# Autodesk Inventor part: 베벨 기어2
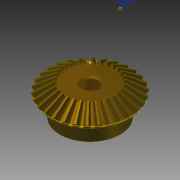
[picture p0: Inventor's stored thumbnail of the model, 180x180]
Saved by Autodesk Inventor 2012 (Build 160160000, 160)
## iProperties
Created: 2012-07
Part Number: 베벨 기어2
Material: Steel, Mild
Document SubType Name: Modeling
Designer: SeoGD™ [www.esajin.kr]
Categories: <?xml version="1.0" encoding="UTF-16"?> <MemberInstance><Categories><FamilyTemplate><FamilyTemplateParameter ValueType="xs:double" Id="1" ObjectReferenceKey="da
Mass: 60.9118 g
Surface Area: 34.3074 cm^2
Volume: 7.7496 cm^3
Density: 7.86 g/cm^3
CustomPartVersion: 1
Author: SeoGD™ [www.esajin.kr]
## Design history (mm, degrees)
node "맨 위 점"
node "메쉬 평면2"
sketch "톱니 본체 스케치"
  geometry: L1 (0, 0)-(28.669, -21.997); L2 (28.669, -21.997)-(31.109, -18.336); L3 (31.109, -18.336)-(0, 0); L4 (30, -20)-(0, 0); L5 (17.219, -13.212)-(18.685, -11.013); L6 (28.669, -21.997)-(17.219, -13.212); L7 (31.109, -18.336)-(18.685, -11.013); L8 (0, -39.387)-(0, 6.564) reference; L9 (0, -20)-(31.109, -20)
  constraints: 16 end point, 4 point on line, 3 perpendicular, 2 collinear, 1 horizontal alignment, 1 vertical alignment
  dimensions: "d0" = 60 diameter of L4.start L8 (= da_de); "d1" = 57.33744 diameter of L1.end L8 (= da_dfe); "d2" = 62.2188 diameter of L2.end L8 (= da_dae); "d3" = 14.4 distance between parallel lines of L2 L5 (= da_b); "d4" = 18.3359 vertical distance of L2.end L1.start (= da_ve)
revolve "톱니 본체" sketch "톱니 본체 스케치" stored, may be unused: angle "d5" = 90 deg
node "시작점"
node "톱니 평면"
sketch "시작 스케치"
  geometry: L1 (0, -23.505)-(0, 10.645) reference; L2 (-0.709, -2.928)-(0.709, -2.928); A1 r 19.188 centre (-19.457, -7.014) between (-0.709, -2.928) and (-3.232, 3.229); A2 r 19.188 centre (19.457, -7.014) between (3.232, 3.229) and (0.709, -2.928); A3 r 57.403 centre (0, -54.083) between (3.232, 3.229) and (-3.232, 3.229); 1 further point
  constraints: 6 point on circle, 3 centre point, 3 symmetric about line, 2 end point, 1 coincident, 1 perpendicular, 1 other
  dimensions: "d7" = 19.18795 radius of A1 (= fd_rr); "d8" = 19.45712 horizontal distance of point (0, -54.083) A1.centre (= fd_x); "d9" = 47.06905 vertical distance of point (0, -54.083) A1.centre (= fd_y); "d57" = 57.40327 radius of A3 (= 0.5 x fd_dva + 0.3 x da_he); "d58" = 51.15527 distance from line of A3.centre L2 (= 0.5 x fd_dva - 1.12 x da_he)
node "끝점"
  node "끝 평면"
sketch "3D 스케치 오른쪽"
  node "Helical Curve Right" dims "d65" = 229.90621 (computed from da_dm, da_delta, da_beta), "d66" = 31.5, "d67" = 60 (= da_de), "d68" = -9.82794 (= -da_delta), "d69" = 8.10972 (computed from fd_loft, da_delta)
node "끝 평면 오른쪽"
sketch "끝 스케치 오른쪽"
  geometry: L1 (0, -41.54)-(0, 13.178) reference; L2 (-0.422, -1.69)-(0.422, -1.69); A1 r 11.427 centre (-11.587, -4.123) between (-0.422, -1.69) and (-1.925, 1.977); A2 r 11.427 centre (11.587, -4.123) between (1.925, 1.977) and (0.422, -1.69); A3 r 34.184 centre (0, -32.153) between (1.925, 1.977) and (-1.925, 1.977); 1 further point
  constraints: 6 point on circle, 3 centre point, 3 symmetric about line, 2 end point, 1 coincident, 1 perpendicular, 1 other
  dimensions: "d70" = 11.58699 horizontal distance of A3.centre A1.centre (computed from fd_x, fd_ratio); "d71" = 28.03028 vertical distance of point (0, -32.153) A1.centre (computed from fd_y, fd_ratio); "d72" = 11.4267 radius of A1 (computed from fd_rr, fd_ratio); "d73" = 30.46369 distance from line of point (0, -32.153) L2 (computed from d58, fd_ratio); "d74" = 34.18446 radius of A3 (computed from d57, fd_ratio)
feature "로프트 오른쪽" sketch "끝 스케치 오른쪽" dims "d75" = 0, "d77" = 0, "d79" = 0, "d80" = 90 deg, "d85" = 20, "d92" = 90 deg, "d93" = 90 deg, "da_teethtype" = 0 [user parameter]
sketch "3D 스케치 왼쪽"
  node "Helical Curve Left" dims "d26" = 229.90621 (computed from da_dm, da_delta, da_beta), "d27" = 8.10972 (computed from fd_loft, da_delta), "d28" = 60 (= da_de), "d29" = -9.82794 (= -da_delta)
node "끝 평면 왼쪽"
sketch "끝 스케치 왼쪽" dims "d56" = 10.3728 (derived)
  geometry: L1 (0, -43.753)-(0, 15.405) reference; L2 (-0.422, -1.678)-(0.422, -1.678); A1 r 11.427 centre (-11.587, -4.111) between (-0.422, -1.678) and (-1.925, 1.988); A2 r 11.427 centre (11.587, -4.111) between (1.925, 1.988) and (0.422, -1.678); A3 r 34.184 centre (0, -32.142) between (1.925, 1.988) and (-1.925, 1.988); 2 further points; 1 other entity
  constraints: 6 point on circle, 3 centre point, 3 symmetric about line, 2 end point, 1 coincident, 2 other
  dimensions: "d30" = 11.4267 radius of A1 (computed from fd_rr, fd_ratio); "d31" = 11.58699 horizontal distance of point (0, -32.142) A1.centre (computed from fd_x, fd_ratio); "d32" = 28.03028 vertical distance of A1.centre point (0, -32.142) (computed from fd_y, fd_ratio); "d61" = 34.18446 radius of A3 (computed from d57, fd_ratio); "d62" = 30.46369 distance from line of point (0, -32.142) L2 (computed from d58, fd_ratio)
feature "로프트 왼쪽" sketch "끝 스케치 왼쪽" dims "d35" = 0, "d37" = 0, "d39" = 0, "d40" = 90 deg, "d84" = 10, "d90" = 90 deg, "d91" = 90 deg, "da_teethtype" = 0 [user parameter]
sketch "본체 스케치"
  geometry: L1 (0, -35.038)-(0, -19.531) reference; L2 (28.669, -21.997)-(17.219, -13.212) reference; L3 (17.219, -13.212)-(0, -13.212); L4 (28.669, -21.997)-(0, -21.997)
  constraints: 4 end point, 2 perpendicular, 2 point on line
revolve "본체 고정" sketch "본체 스케치" stored, may be unused: angle "d46" = 90 deg
sketch "Sketch6"
  geometry: L1 (30, -20)-(0, 0) reference; L2 (0, -37.8)-(0, 6.3) reference
feature "피치 지름" sketch "Sketch6" dims angle "d47" = 90 deg
sketch "스케치8"
  geometry: C1 r 22.5 at (0, 0); 1 further point
  constraints: 1 centre point, 1 coincident
  dimensions: "d94" = 45 diameter of C1
extrude "돌출1" join sketch "스케치8" distance "d95" = 13; taper "d96" = 0 deg
sketch "스케치9"
  geometry: 1 further point
hole "구멍1" sketch "스케치9" at (0, 0) diameter "d97" = 12; stored, may be unused: countersink angle "d101" = 90 deg, drill point angle "d103" = 118 deg; dims "d98" = 6, "d99" = 4, "d100" = 2, "d102" = 8
sketch "스케치10"
  geometry: L1 (5.657, 2)-(7.8, 2); L2 (7.8, 2)-(7.8, -2); L3 (7.8, -2)-(5.657, -2); A1 r 6 centre (0, 0) between (5.657, 2) and (5.657, -2) reference; 1 further point
  constraints: 6 end point, 2 parallel, 2 point on circle, 1 horizontal, 1 perpendicular
  dimensions: "d104" = 4 distance of L1.end L2.end; "d112" = 13.8 dimension on A1 L2
extrude "돌출2" cut sketch "스케치10" stored distance "d106" = 10; taper "d107" = 0 deg
chamfer "모따기1" distance "d108" = 1; stored, may be unused: second distance "d109" = 2, angle "d110" = 45 deg
fillet "모깎기1" dims "d111" = 2
body "Solid1"
feature "로프트" dims "d17" = 0, "d18" = 90 deg, "d19" = 0, "d20" = 90 deg, "d89" = 0, "da_teethtype" = 0 [user parameter]
pattern_circular "원형 패턴" dims angle "d22" = 360 deg, "d88" = 0, "da_teethtype" = 0 [user parameter]
pattern_circular "원형 패턴 오른쪽" dims angle "d82" = 360 deg, "da_teethtype" = 0 [user parameter]
pattern_circular "원형 패턴 왼쪽" dims angle "d42" = 360 deg, "da_teethtype" = 0 [user parameter]
sketch "끝 스케치"
  geometry: L1 (0, -15.359)-(0, 6.983) reference; L2 (-0.422, -1.69)-(0.422, -1.69); A1 r 11.427 centre (-11.587, -4.123) between (-0.422, -1.69) and (-1.925, 1.977); A2 r 11.427 centre (11.587, -4.123) between (1.925, 1.977) and (0.422, -1.69); A3 r 34.184 centre (0, -32.153) between (1.925, 1.977) and (-1.925, 1.977); 1 further point
  constraints: 6 point on circle, 3 centre point, 3 symmetric about line, 2 end point, 1 coincident, 1 other
  dimensions: "d12" = 11.4267 radius of A1 (computed from fd_rr, fd_ratio); "d15" = 11.58699 horizontal distance of A1.centre point (0, -32.153) (computed from fd_x, fd_ratio); "d16" = 28.03028 vertical distance of A1.centre point (0, -32.153) (computed from fd_y, fd_ratio); "d59" = 34.18446 radius of A3 (computed from d57, fd_ratio); "d60" = 30.46369 distance from line of A3.centre L2 (computed from d58, fd_ratio)
body "Srf1"
other parameters: "da_b" = 14.4 [user parameter; used in 2 equation terms], "da_de" = 60 [user parameter; used in 4 equation terms], "da_dae" = 62.2188 [user parameter; used in 2 equation terms], "da_dfe" = 57.33744 [user parameter; used in 1 equation term], "da_le" = 36.05551 [user parameter; used in 1 equation term], "da_omega" = 90 deg [user parameter; used in 1 equation term], "da_beta" = 0 [user parameter; used in 2 equation terms], "da_delta" = 9.82794 [user parameter; used in 8 equation terms], "da_alpha" = 20 deg [user parameter; used in 2 equation terms], "da_he" = 4.4 [user parameter; used in 4 equation terms], "da_ve" = 18.3359 [user parameter; used in 1 equation term], "fd_dv" = 108.16654 (computed from da_de, da_delta) [user parameter; used in 1 equation term], "fd_dva" = 112.16654 (computed from da_dae, da_delta) [user parameter; used in 3 equation terms], "fd_dvb" = 101.6433 (computed from fd_dv, da_alpha) [user parameter; used in 2 equation terms], "da_zv" = 540.83269 [user parameter; used in 1 equation term], "fd_loft" = 14.62 (= da_b + 0.05 x da_he) [user parameter; used in 4 equation terms], "fd_ratio" = 5.95514 (computed from da_le, fd_loft) [user parameter; used in 15 equation terms], "fd_rr" = 19.18795 (computed from fd_dd, fd_dvb) [user parameter; used in 6 equation terms], "fd_angle" = 0.29367 (computed from da_zv) [user parameter; used in 4 equation terms], "fd_x1" = 1.58802 (computed from da_dvw, fd_angle) [user parameter; used in 1 equation term], "fd_y1" = 54.05995 (computed from da_dvw, fd_angle) [user parameter; used in 1 equation term], "fd_x2" = 17.8691 (computed from fd_rr, fd_angle2, fd_angle) [user parameter; used in 1 equation term], "fd_y2" = 6.9909 (computed from fd_rr, fd_angle2, fd_angle) [user parameter; used in 1 equation term], "fd_x" = 19.45712 (= fd_x1 + fd_x2) [user parameter; used in 4 equation terms], "fd_y" = 47.06905 (= fd_y1 - fd_y2) [user parameter; used in 4 equation terms], "fd_angle2" = 3.43555 (computed from fd_dvb, fd_dd, da_alpha) [user parameter; used in 2 equation terms], "fd_dd" = 108.64654 (= fd_dva - 0.8 x da_he) [user parameter; used in 2 equation terms], "da_dvw" = 108.16654 [user parameter; used in 2 equation terms], "d11" = 14.62 (= fd_loft), "da_dm" = 48.01848 [user parameter; used in 2 equation terms], "da_x" = 0 [user parameter], "da_m" = 2 [user parameter], "d48" = 0, "d49" = 0, "d50" = 90 deg (= da_omega), "d51" = 6 deg (computed from da_z), "d52" = 0, "d53" = 0, "d54" = 0
